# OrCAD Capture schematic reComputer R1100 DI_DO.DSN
size A3; rev: v1.0
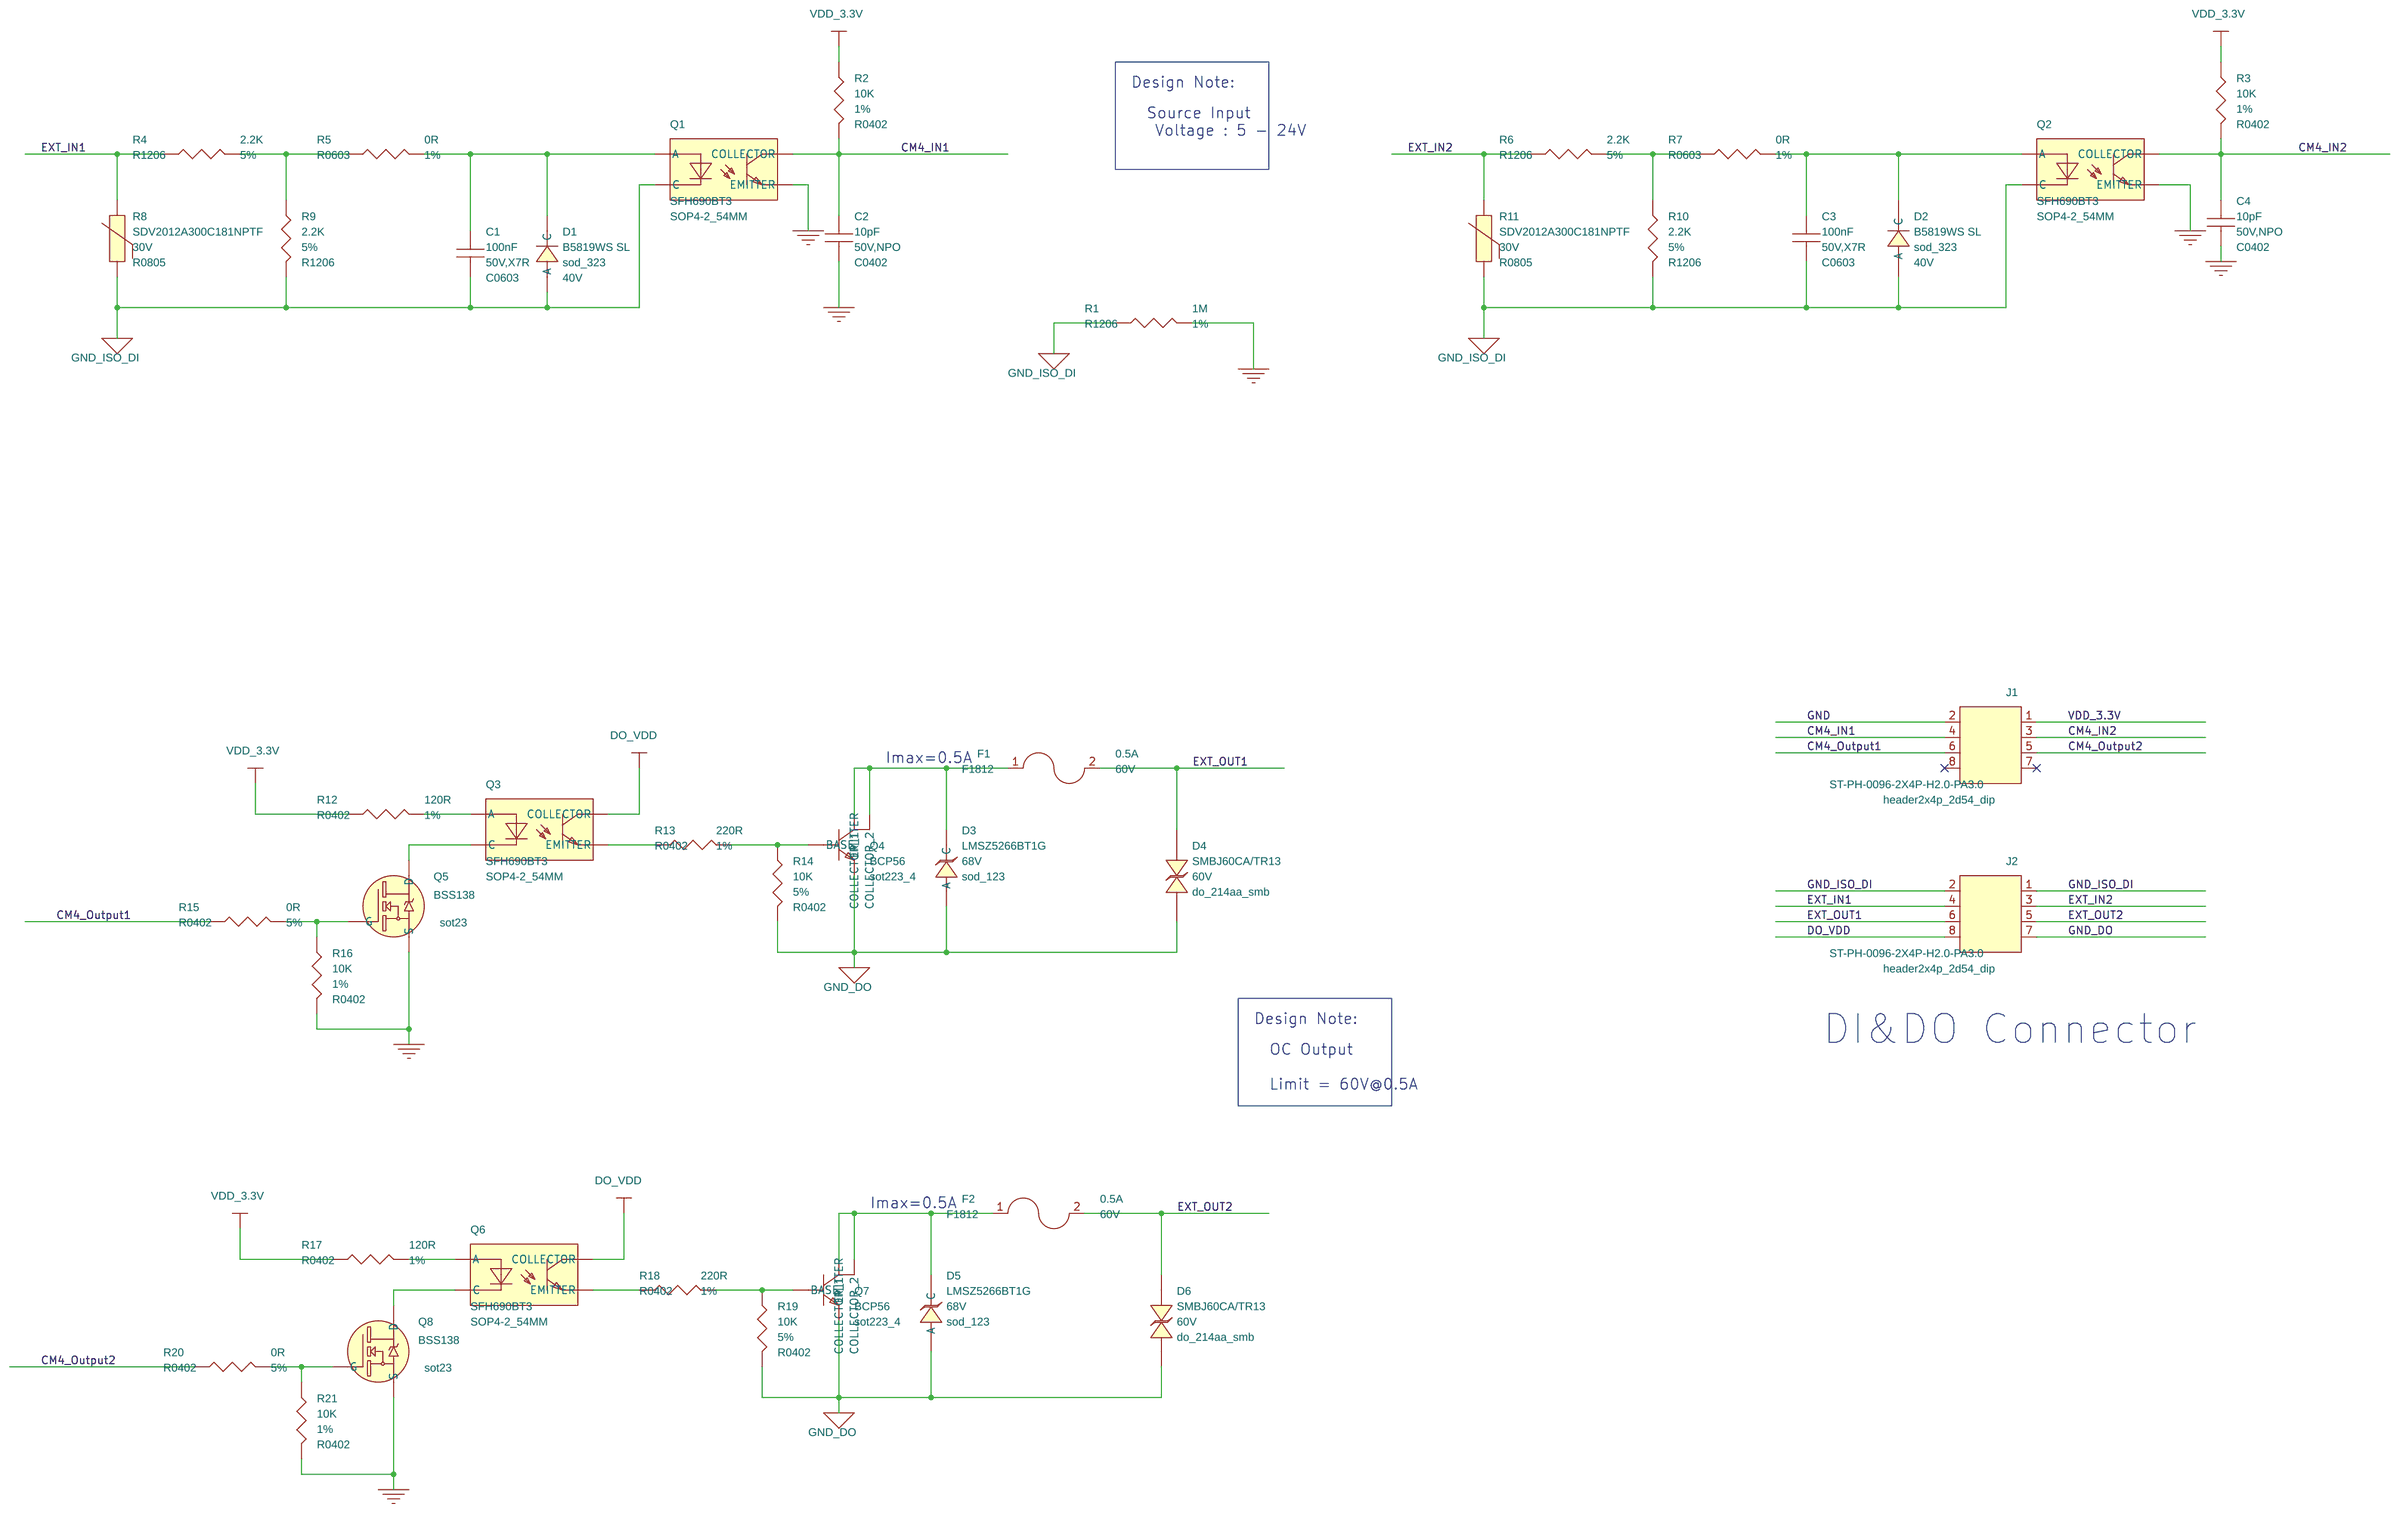
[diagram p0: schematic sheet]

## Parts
C1  100nF  [C0603]
C2  10pF  [C0402]
C3  100nF  [C0603]
C4  10pF  [C0402]
D1  B5819WS SL  [sod_323]
D2  B5819WS SL  [sod_323]
D3  LMSZ5266BT1G  [sod_123]
D4  SMBJ60CA/TR13  [do_214aa_smb]
D5  LMSZ5266BT1G  [sod_123]
D6  SMBJ60CA/TR13  [do_214aa_smb]
F1  0.5A  [F1812]
F2  0.5A  [F1812]
J1  ST-PH-0096-2X4P-H2.0-PA3.0  [header2x4p_2d54_dip]
J2  ST-PH-0096-2X4P-H2.0-PA3.0  [header2x4p_2d54_dip]
Q1  SFH690BT3  [SOP4-2_54MM]
Q2  SFH690BT3  [SOP4-2_54MM]
Q3  SFH690BT3  [SOP4-2_54MM]
Q4  BCP56  [sot223_4]
Q5  BSS138  [sot23]
Q6  SFH690BT3  [SOP4-2_54MM]
Q7  BCP56  [sot223_4]
Q8  BSS138  [sot23]
R1  1M  [R1206]
R2  10K  [R0402]
R3  10K  [R0402]
R4  2.2K  [R1206]
R5  0R  [R0603]
R6  2.2K  [R1206]
R7  0R  [R0603]
R8  SDV2012A300C181NPTF  [R0805]
R9  2.2K  [R1206]
R10  2.2K  [R1206]
R11  SDV2012A300C181NPTF  [R0805]
R12  120R  [R0402]
R13  220R  [R0402]
R14  10K  [R0402]
R15  0R  [R0402]
R16  10K  [R0402]
R17  120R  [R0402]
R18  220R  [R0402]
R19  10K  [R0402]
R20  0R  [R0402]
R21  10K  [R0402]

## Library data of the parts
C1 C3 = CC: SMD CAP Ceramic 100nF-50V-10%-X7R;0603; Manufacturer: YAGEO; Manufacturer Part Number: CC0603KRX7R9BB104; PN: 302010138; Part Type: Ceramic; Rating: 50V,X7R; Status: BeagleBone Carrier Board; Temperature: -55°C to 125°C
C2 C4 = CC: SMD CAP Ceramic 10pF-50V-5%-NPO;0402; Manufacturer: YAGEO; Manufacturer Part Number: CC0402JRNPO9BN100; PN: 302010001; Part Type: Ceramic; Rating: 50V,NPO; Status: BeagleBone Carrier Board; Temperature: -55°C to 125°C
D1 D2 = D: SMD Diode Schottky 40V-1A;SOD-323; Manufacturer: CJ; PN: 304011053; Part Type: Schottky Diode; Rating: 40V; Status: reTerminal DM
D3 D5 = DIODE_TVS: SMD Diode Zener;68V-64.6V to 71.4V-500mW;SOD-123; Manufacturer: CJ; PN: TMP-747; Package Size: SOD-123; Rating: 68V; Status: ReComputer R1100; Temperature: -55°C to 150°C
D4 D6 = DIODE_TVS_BI-DIR: SMD Diode TVS 60VWM-96.8V;DO-214AA(SMB); Manufacturer: BrightKing; PN: TMP-748; Package Size: SMB; Rating: 60V; Status: ReComputer R1100; Temperature: -65°C to 150°C
F1 F2 = Fuse: SMD PPTC 500mA-1A-60V;1812; Manufacturer: JK; Manufacturer Part Number: JK-MSMD050-60; PN: 307010738; Package Size: 1812; Rating: 60V; Status: reComputer Industrial J201; Temperature: - 40 °C to 85 °C
J1 J2 = Header_2X4: DIP Black Male Header VERT;2*4P-2.54-2.0-10.16/3.0mm; Manufacturer: 思拓展; PN: TMP-756; Package Size: 2*4P-2.54-3.0mm; Rating: 3A; Status: reComputer R1100; Temperature: -40°C to 105°C
Q1-Q3 Q6 = Optoisolator_4P: SMD IC OPTOISOLATOR;4SOP; Manufacturer: Vishay; PN: 310990465; Part Type: OPTOISOLATOR; Status: Combox Pro; Temperature: -55°C to 100°C
Q4 Q7 = NPN_4P: SMD Transistor NPN 80V-1A; Manufacturer: CJ; PN: 305010724; Part Type: NPN; Rating: 80V,1A; Status: reTerminal Plus; Temperature: -55°C to 150°C
Q5 Q8 = NMOS_123: SMD MOSFET N-CH 50V-220mA;SOT-23; Manufacturer: CJ; PN: 305031521; Part Type: NMOS; Rating: 50V;220mA; Status: reTerminal DM
R1 = R: SMD RES 1M-1%-1/4W;1206; Manufacturer: YAGEO; Manufacturer Part Number: RC1206FR-071ML; PN: 301010410; Part Type: RES; Rating: 1%; Status: Sensecap Gateway V1; Temperature: -55°C to 155°C
R2 R3 R16 R21 = R: SMD RES 10K-1%-1/16W;0402; Manufacturer: YAGEO; Manufacturer Part Number: RC0402FR-0710KL; PN: 301010047; Part Type: RES; Rating: 1%; Status: BeagleBone Carrier Board; Temperature: -55°C to 155°C
R4 R6 R9 R10 = R: SMD RES 2.2K-5%-1/4W;1206; Manufacturer: YAGEO; Manufacturer Part Number: RC1206JR-072K2L; PN: 301010726; Part Type: RES; Rating: 5%; Status: Zola Gateway; Temperature: -55°C to 155°C
R5 R7 = R: SMD RES 0R-1%-1/10W;0603; Manufacturer: YAGEO; Manufacturer Part Number: RC0603FR-070RL; PN: 301012029; Part Type: RES; Rating: 1%; Status: BBG Gateway; Temperature: -55°C to 155°C
R8 R11 = VDR: SMD RES Varistor 21.3V-65V;0805-L2*W1.25*H0.85mm; Manufacturer: Sunlord; PN: 314130268; Part Type: Varistor; Rating: 30V; Status: reTerminal DM
R12 R17 = R: SMD RES;120R-1%-1/16W-0402; Manufacturer: YAGEO; Manufacturer Part Number: RC0402FR-07120RL; PN: 301010626; Part Type: RES; Rating: 1%; Status: reTerminal DM; Temperature: -55°C to 155°C
R13 R18 = R: SMD RES-220R-1%-1/16W;0402; Manufacturer: YAGEO; Manufacturer Part Number: RC0402FR-07220RL; PN: 301010521; Package Size: 0402; Rating: 1%; Status: Amazon Sidewalk Module; Temperature: -55°C to 155°C
R14 R19 = R: SMD RES 10K-5%-1/16W;0402; Manufacturer: YAGEO; Manufacturer Part Number: RC0402JR-0710KL; PN: 301010004; Part Type: RES; Rating: 5%; Status: BeagleBone Carrier Board; Temperature: -55°C to 155°C
R15 R20 = R: SMD RES 0R-5%-1/16W;0402; Manufacturer: YAGEO; Manufacturer Part Number: RC0402JR-070RL; PN: 301010000; Part Type: RES; Rating: 5%; Status: BeagleBone Carrier Board; Temperature: -55°C to 155°C; Datasheet: Y:\01_Cadence_Library\05_Datasheet\301010000_YAGEO_RC0402JR-070RL_Datasheet.pdf

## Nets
GND: C2.2 C4.2 J1.2 Q1.3(EMITTER) Q2.3(EMITTER) Q5.2(S) Q8.2(S) R1.2 R16.2 R21.2
GND_DO: D3.1(A) D4.1 D5.1(A) D6.1 J2.7 Q4.3(EMITTER) Q7.3(EMITTER) R14.2 R19.2
GND_ISO_DI: C1.2 C3.2 D1.1(A) D2.1(A) J2.1 J2.2 Q1.2(C) Q2.2(C) R1.1 R8.2 R9.2 R10.2 R11.2
VDD_3.3V: J1.1 R2.1 R3.1 R12.1 R17.1
CM4_IN1: C2.1 J1.4 Q1.4(COLLECTOR) R2.2
CM4_IN2: C4.1 J1.3 Q2.4(COLLECTOR) R3.2
CM4_Output1: J1.6 R15.1
CM4_Output2: J1.5 R20.1
DO_VDD: J2.8 Q3.4(COLLECTOR) Q6.4(COLLECTOR)
EXT_IN1: J2.4 R4.1 R8.1
EXT_IN2: J2.3 R6.1 R11.1
EXT_OUT1: D4.2 F1.2 J2.6
EXT_OUT2: D6.2 F2.2 J2.5
N12939: R4.2 R5.1 R9.1
N12951: C1.1 D1.2(C) Q1.1(A) R5.2
N12997: R6.2 R7.1 R10.1
N13009: C3.1 D2.2(C) Q2.1(A) R7.2
N14695: D3.2(C) F1.1 Q4.2(COLLECTOR_1) Q4.4(COLLECTOR_2)
N14789: Q3.1(A) R12.2
N14847: Q3.2(C) Q5.3(D)
N14855: Q3.3(EMITTER) R13.1
N14859: Q4.1(BASE) R13.2 R14.1
N15023: Q5.1(G) R15.2 R16.1
N15163: D5.2(C) F2.1 Q7.2(COLLECTOR_1) Q7.4(COLLECTOR_2)
N15257: Q6.1(A) R17.2
N15315: Q6.2(C) Q8.3(D)
N15323: Q6.3(EMITTER) R18.1
N15327: Q7.1(BASE) R18.2 R19.1
N15491: Q8.1(G) R20.2 R21.1

Not connected (* = marked no-connect by the designer): J1 7* 8*

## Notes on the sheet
- Design Note:
- Source Input
   Voltage : 5 - 24V
- Imax=0.5A
- Design Note:
- DI&DO Connector
- OC Output
  Limit = 60V@0.5A
- Imax=0.5A
